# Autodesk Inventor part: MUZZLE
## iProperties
Created: 2010-11
Part Number: MUZZLE
Document SubType Name: Modeling
Designer: ROBERT
Density: 1 g/cm^3
Author: ROBERT
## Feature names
1. Extrusion1
2. Extrusion2
3. Extrusion3
4. Extrusion4
5. Extrusion5
6. Extrusion6
7. Fillet1
8. Fillet2
9. Fillet3
10. Fillet4
11. Fillet5
12. Fillet6
13. Fillet7
14. Fillet8
